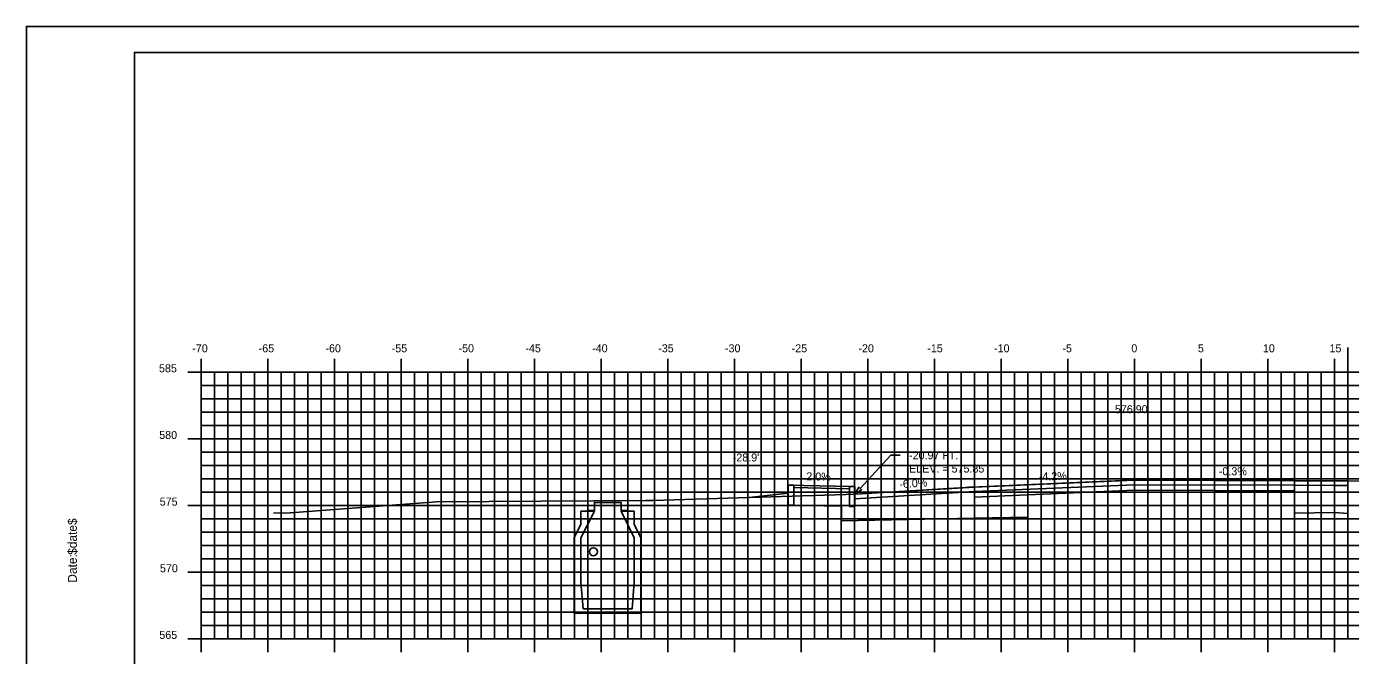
# Model space of a CAD drawing. Extents: x 1048345 to 1048515, y 781148 to 781258.
# Drawn here: x 1048344.7 to 1048444, y 781211 to 781258.2 of the extents above; entities that cross this region are included whole.
import ezdxf

# ---------------------------------------------------------------- set-up
doc = ezdxf.new("R2010")
doc.units = 0
for name, color, linetype in [('ANNOTATION', 7, 'Continuous'), ('BORDER', 7, 'Continuous'), ('D_Curb_Type1_Lt', 7, 'Continuous'), ('D_Roadway_Centerline', 7, 'Continuous'), ('D_Roadway_Centerline_Text', 7, 'Continuous'), ('D_Roadway_Edge_Shoulder', 7, 'Continuous'), ('D_Roadway_Edge_TW', 7, 'Continuous'), ('D_Roadway_Pavement', 7, 'Continuous'), ('D_Roadway_Sidewalks_Paved', 7, 'Continuous'), ('D_Roadway_SubGrade', 7, 'Continuous'), ('D_Text_Standard', 7, 'Continuous'), ('E_ROW_Line', 7, 'Continuous'), ('H_V ANNOTATION', 7, 'Continuous'), ('MAJOR', 7, 'Continuous'), ('MINOR', 7, 'Continuous'), ('PLOT BOUNDARY', 7, 'Continuous'), ('S_Drainage_CB', 7, 'Continuous'), ('S_Drainage_Invert', 7, 'Continuous'), ('S_Roadway_Centerline', 7, 'Continuous')]:
    doc.layers.add(name, color=color, linetype=linetype)

msp = doc.modelspace()

# ---------------------------------------------------------------- linework, layer by layer
at = {"layer": 'BORDER'}
msp.add_lwpolyline([(1048352.833, 781151.252), (1048512.833, 781151.252), (1048512.833, 781256.252), (1048352.833, 781256.252)], close=True, dxfattribs=at)
at = {"layer": 'D_Curb_Type1_Lt'}
for points in [[(1048401.863, 781223.78), (1048401.863, 781222.28), (1048402.28, 781222.28), (1048402.28, 781223.78)], [(1048406.445, 781223.686), (1048406.445, 781222.186), (1048406.862, 781222.186), (1048406.862, 781223.686)], [(1048406.445, 781223.686), (1048406.445, 781222.186), (1048406.862, 781222.186), (1048406.862, 781223.686)]]:
    msp.add_lwpolyline(points, close=True, dxfattribs=at)
at = {"layer": 'D_Roadway_Edge_Shoulder'}
for p, q in [((1048415.832, 781223.645), (1048406.863, 781223.102)), ((1048415.832, 781223.311), (1048406.864, 781222.769))]:
    msp.add_line(p, q, dxfattribs=at)
msp.add_lwpolyline([(1048439.832, 781224.113), (1048442.832, 781224.104), (1048443.832, 781224.101), (1048443.832, 781223.767), (1048442.832, 781223.77), (1048439.832, 781223.779)], close=True, dxfattribs=at)
at = {"layer": 'D_Roadway_Edge_TW'}
msp.add_lwpolyline([(1048415.832, 781223.311), (1048415.832, 781223.645), (1048427.832, 781224.149), (1048439.832, 781224.113), (1048439.832, 781223.779), (1048427.832, 781223.815)], close=True, dxfattribs=at)
at = {"layer": 'D_Roadway_Pavement'}
msp.add_lwpolyline([(1048415.832, 781222.895), (1048415.832, 781223.311), (1048427.832, 781223.815), (1048439.832, 781223.779), (1048439.832, 781223.363), (1048427.832, 781223.399)], close=True, dxfattribs=at)
at = {"layer": 'D_Roadway_Sidewalks_Paved'}
for points in [[(1048406.562, 781223.686), (1048401.863, 781223.78), (1048401.863, 781223.613)], [(1048406.562, 781223.686), (1048401.863, 781223.78), (1048401.863, 781223.613)], [(1048402.28, 781223.605), (1048406.445, 781223.521)], [(1048402.28, 781223.605), (1048406.445, 781223.521)]]:
    msp.add_lwpolyline(points, dxfattribs=at)
at = {"layer": 'D_Roadway_SubGrade'}
for p, q in [((1048401.863, 781223.78), (1048401.863, 781222.28)), ((1048443.832, 781224.101), (1048443.832, 781221.671)), ((1048401.863, 781223.196), (1048398.941, 781222.864)), ((1048401.863, 781222.28), (1048405.863, 781222.2)), ((1048405.863, 781222.2), (1048405.864, 781222.177))]:
    msp.add_line(p, q, dxfattribs=at)
for points in [[(1048415.832, 781223.311), (1048415.832, 781222.895), (1048419.832, 781223.063), (1048419.832, 781221.396), (1048415.832, 781221.316), (1048405.864, 781221.116), (1048405.864, 781222.177)], [(1048443.832, 781221.671), (1048442.832, 781221.747), (1048439.832, 781221.696), (1048439.832, 781223.779), (1048439.832, 781223.779), (1048442.832, 781223.77), (1048443.832, 781223.767), (1048443.832, 781223.184)]]:
    msp.add_lwpolyline(points, dxfattribs=at)
at = {"layer": 'D_Text_Standard'}
msp.add_lwpolyline([(1048407.258, 781223.53), (1048409.564, 781226.03), (1048410.244, 781226.03)], dxfattribs=at)
msp.add_lwpolyline([(1048406.863, 781223.102), (1048407.151, 781223.629), (1048407.365, 781223.431)], close=True, dxfattribs=at)
at = {"layer": 'E_ROW_Line'}
msp.add_line((1048443.832, 781224.101), (1048443.832, 781234.101), dxfattribs=at)
at = {"layer": 'MAJOR'}
for p, q in [((1048357.832, 781233.254), (1048357.832, 781232.252)), ((1048362.832, 781233.254), (1048362.832, 781232.252)), ((1048367.832, 781233.254), (1048367.832, 781232.252)), ((1048372.832, 781233.254), (1048372.832, 781232.252)), ((1048377.832, 781233.254), (1048377.832, 781232.252)), ((1048382.832, 781233.254), (1048382.832, 781232.252)), ((1048387.832, 781233.254), (1048387.832, 781232.252)), ((1048392.832, 781233.254), (1048392.832, 781232.252)), ((1048397.832, 781233.254), (1048397.832, 781232.252)), ((1048402.832, 781233.254), (1048402.832, 781232.252)), ((1048407.832, 781233.254), (1048407.832, 781232.252)), ((1048412.832, 781233.254), (1048412.832, 781232.252)), ((1048417.832, 781233.254), (1048417.832, 781232.252)), ((1048422.832, 781233.254), (1048422.832, 781232.252)), ((1048427.832, 781233.254), (1048427.832, 781232.252)), ((1048432.832, 781233.254), (1048432.832, 781232.252)), ((1048437.832, 781233.254), (1048437.832, 781232.252)), ((1048442.832, 781233.254), (1048442.832, 781232.252)), ((1048356.83, 781232.252), (1048357.832, 781232.252)), ((1048357.832, 781232.252), (1048497.832, 781232.252)), ((1048357.832, 781212.252), (1048357.832, 781232.252)), ((1048357.832, 781212.252), (1048357.832, 781232.252)), ((1048357.832, 781232.252), (1048497.832, 781232.252)), ((1048362.832, 781212.252), (1048362.832, 781232.252)), ((1048367.832, 781212.252), (1048367.832, 781232.252)), ((1048372.832, 781212.252), (1048372.832, 781232.252)), ((1048377.832, 781212.252), (1048377.832, 781232.252)), ((1048382.832, 781212.252), (1048382.832, 781232.252)), ((1048387.832, 781212.252), (1048387.832, 781232.252)), ((1048392.832, 781212.252), (1048392.832, 781232.252)), ((1048397.832, 781212.252), (1048397.832, 781232.252)), ((1048402.832, 781212.252), (1048402.832, 781232.252)), ((1048407.832, 781212.252), (1048407.832, 781232.252)), ((1048412.832, 781212.252), (1048412.832, 781232.252)), ((1048417.832, 781212.252), (1048417.832, 781232.252)), ((1048422.832, 781212.252), (1048422.832, 781232.252)), ((1048427.832, 781212.252), (1048427.832, 781232.252)), ((1048432.832, 781212.252), (1048432.832, 781232.252)), ((1048437.832, 781212.252), (1048437.832, 781232.252)), ((1048442.832, 781212.252), (1048442.832, 781232.252)), ((1048356.83, 781227.252), (1048357.832, 781227.252)), ((1048357.832, 781227.252), (1048497.832, 781227.252)), ((1048356.83, 781222.252), (1048357.832, 781222.252)), ((1048357.832, 781222.252), (1048497.832, 781222.252)), ((1048356.83, 781217.252), (1048357.832, 781217.252)), ((1048357.832, 781217.252), (1048497.832, 781217.252)), ((1048356.83, 781212.252), (1048357.832, 781212.252)), ((1048357.832, 781212.252), (1048497.832, 781212.252)), ((1048357.832, 781212.252), (1048497.832, 781212.252)), ((1048357.832, 781211.25), (1048357.832, 781212.252)), ((1048362.832, 781211.25), (1048362.832, 781212.252)), ((1048367.832, 781211.25), (1048367.832, 781212.252)), ((1048372.832, 781211.25), (1048372.832, 781212.252)), ((1048377.832, 781211.25), (1048377.832, 781212.252)), ((1048382.832, 781211.25), (1048382.832, 781212.252)), ((1048387.832, 781211.25), (1048387.832, 781212.252)), ((1048392.832, 781211.25), (1048392.832, 781212.252)), ((1048397.832, 781211.25), (1048397.832, 781212.252)), ((1048402.832, 781211.25), (1048402.832, 781212.252)), ((1048407.832, 781211.25), (1048407.832, 781212.252)), ((1048412.832, 781211.25), (1048412.832, 781212.252)), ((1048417.832, 781211.25), (1048417.832, 781212.252)), ((1048422.832, 781211.25), (1048422.832, 781212.252)), ((1048427.832, 781211.25), (1048427.832, 781212.252)), ((1048432.832, 781211.25), (1048432.832, 781212.252)), ((1048437.832, 781211.25), (1048437.832, 781212.252)), ((1048442.832, 781211.25), (1048442.832, 781212.252))]:
    msp.add_line(p, q, dxfattribs=at)
at = {"layer": 'MINOR'}
for p, q in [((1048358.832, 781212.252), (1048358.832, 781232.252)), ((1048359.832, 781212.252), (1048359.832, 781232.252)), ((1048360.832, 781212.252), (1048360.832, 781232.252)), ((1048361.832, 781212.252), (1048361.832, 781232.252)), ((1048363.832, 781212.252), (1048363.832, 781232.252)), ((1048364.832, 781212.252), (1048364.832, 781232.252)), ((1048365.832, 781212.252), (1048365.832, 781232.252)), ((1048366.832, 781212.252), (1048366.832, 781232.252)), ((1048368.832, 781212.252), (1048368.832, 781232.252)), ((1048369.832, 781212.252), (1048369.832, 781232.252)), ((1048370.832, 781212.252), (1048370.832, 781232.252)), ((1048371.832, 781212.252), (1048371.832, 781232.252)), ((1048373.832, 781212.252), (1048373.832, 781232.252)), ((1048374.832, 781212.252), (1048374.832, 781232.252)), ((1048375.832, 781212.252), (1048375.832, 781232.252)), ((1048376.832, 781212.252), (1048376.832, 781232.252)), ((1048378.832, 781212.252), (1048378.832, 781232.252)), ((1048379.832, 781212.252), (1048379.832, 781232.252)), ((1048380.832, 781212.252), (1048380.832, 781232.252)), ((1048381.832, 781212.252), (1048381.832, 781232.252)), ((1048383.832, 781212.252), (1048383.832, 781232.252)), ((1048384.832, 781212.252), (1048384.832, 781232.252)), ((1048385.832, 781212.252), (1048385.832, 781232.252)), ((1048386.832, 781212.252), (1048386.832, 781232.252)), ((1048388.832, 781212.252), (1048388.832, 781232.252)), ((1048389.832, 781212.252), (1048389.832, 781232.252)), ((1048390.832, 781212.252), (1048390.832, 781232.252)), ((1048391.832, 781212.252), (1048391.832, 781232.252)), ((1048393.832, 781212.252), (1048393.832, 781232.252)), ((1048394.832, 781212.252), (1048394.832, 781232.252)), ((1048395.832, 781212.252), (1048395.832, 781232.252)), ((1048396.832, 781212.252), (1048396.832, 781232.252)), ((1048398.832, 781212.252), (1048398.832, 781232.252)), ((1048399.832, 781212.252), (1048399.832, 781232.252)), ((1048400.832, 781212.252), (1048400.832, 781232.252)), ((1048401.832, 781212.252), (1048401.832, 781232.252)), ((1048403.832, 781212.252), (1048403.832, 781232.252)), ((1048404.832, 781212.252), (1048404.832, 781232.252)), ((1048405.832, 781212.252), (1048405.832, 781232.252)), ((1048406.832, 781212.252), (1048406.832, 781232.252)), ((1048408.832, 781212.252), (1048408.832, 781232.252)), ((1048409.832, 781212.252), (1048409.832, 781232.252)), ((1048410.832, 781212.252), (1048410.832, 781232.252)), ((1048411.832, 781212.252), (1048411.832, 781232.252)), ((1048413.832, 781212.252), (1048413.832, 781232.252)), ((1048414.832, 781212.252), (1048414.832, 781232.252)), ((1048415.832, 781212.252), (1048415.832, 781232.252)), ((1048416.832, 781212.252), (1048416.832, 781232.252)), ((1048418.832, 781212.252), (1048418.832, 781232.252)), ((1048419.832, 781212.252), (1048419.832, 781232.252)), ((1048420.832, 781212.252), (1048420.832, 781232.252)), ((1048421.832, 781212.252), (1048421.832, 781232.252)), ((1048423.832, 781212.252), (1048423.832, 781232.252)), ((1048424.832, 781212.252), (1048424.832, 781232.252)), ((1048425.832, 781212.252), (1048425.832, 781232.252)), ((1048426.832, 781212.252), (1048426.832, 781232.252)), ((1048428.832, 781212.252), (1048428.832, 781232.252)), ((1048429.832, 781212.252), (1048429.832, 781232.252)), ((1048430.832, 781212.252), (1048430.832, 781232.252)), ((1048431.832, 781212.252), (1048431.832, 781232.252)), ((1048433.832, 781212.252), (1048433.832, 781232.252)), ((1048434.832, 781212.252), (1048434.832, 781232.252)), ((1048435.832, 781212.252), (1048435.832, 781232.252)), ((1048436.832, 781212.252), (1048436.832, 781232.252)), ((1048438.832, 781212.252), (1048438.832, 781232.252)), ((1048439.832, 781212.252), (1048439.832, 781232.252)), ((1048440.832, 781212.252), (1048440.832, 781232.252)), ((1048441.832, 781212.252), (1048441.832, 781232.252)), ((1048443.832, 781212.252), (1048443.832, 781232.252)), ((1048357.832, 781231.252), (1048497.832, 781231.252)), ((1048357.832, 781231.252), (1048358.834, 781231.252)), ((1048357.832, 781230.252), (1048497.832, 781230.252)), ((1048357.832, 781230.252), (1048358.834, 781230.252)), ((1048357.832, 781229.252), (1048497.832, 781229.252)), ((1048357.832, 781229.252), (1048358.834, 781229.252)), ((1048357.832, 781228.252), (1048497.832, 781228.252)), ((1048357.832, 781228.252), (1048358.834, 781228.252)), ((1048357.832, 781226.252), (1048497.832, 781226.252)), ((1048357.832, 781226.252), (1048358.834, 781226.252)), ((1048357.832, 781225.252), (1048497.832, 781225.252)), ((1048357.832, 781225.252), (1048358.834, 781225.252)), ((1048357.832, 781224.252), (1048497.832, 781224.252)), ((1048357.832, 781224.252), (1048358.834, 781224.252)), ((1048357.832, 781223.252), (1048497.832, 781223.252)), ((1048357.832, 781223.252), (1048358.834, 781223.252)), ((1048357.832, 781221.252), (1048497.832, 781221.252)), ((1048357.832, 781221.252), (1048358.834, 781221.252)), ((1048357.832, 781220.252), (1048497.832, 781220.252)), ((1048357.832, 781220.252), (1048358.834, 781220.252)), ((1048357.832, 781219.252), (1048497.832, 781219.252)), ((1048357.832, 781219.252), (1048358.834, 781219.252)), ((1048357.832, 781218.252), (1048497.832, 781218.252)), ((1048357.832, 781218.252), (1048358.834, 781218.252)), ((1048357.832, 781216.252), (1048497.832, 781216.252)), ((1048357.832, 781216.252), (1048358.834, 781216.252)), ((1048357.832, 781215.252), (1048497.832, 781215.252)), ((1048357.832, 781215.252), (1048358.834, 781215.252)), ((1048357.832, 781214.252), (1048497.832, 781214.252)), ((1048357.832, 781214.252), (1048358.834, 781214.252)), ((1048357.832, 781213.252), (1048497.832, 781213.252)), ((1048357.832, 781213.252), (1048358.834, 781213.252))]:
    msp.add_line(p, q, dxfattribs=at)
at = {"layer": 'PLOT BOUNDARY'}
msp.add_lwpolyline([(1048344.739, 781148.193), (1048514.739, 781148.193), (1048514.739, 781258.193), (1048344.739, 781258.193)], close=True, dxfattribs=at)
at = {"layer": 'S_Drainage_CB'}
for p, q in [((1048386.314, 781220.848), (1048386.314, 781221.832)), ((1048386.314, 781221.832), (1048387.331, 781221.832)), ((1048387.331, 781221.832), (1048386.314, 781219.831)), ((1048389.332, 781221.832), (1048390.316, 781221.832)), ((1048390.316, 781219.831), (1048389.332, 781221.832)), ((1048390.316, 781221.832), (1048390.316, 781220.848)), ((1048385.822, 781219.831), (1048386.314, 781220.848)), ((1048390.316, 781220.848), (1048390.809, 781219.831)), ((1048385.822, 781214.188), (1048385.822, 781219.831)), ((1048386.314, 781219.831), (1048386.314, 781216.517)), ((1048390.316, 781216.517), (1048390.316, 781219.831)), ((1048390.809, 781219.831), (1048390.809, 781214.188)), ((1048386.314, 781216.517), (1048386.478, 781214.516)), ((1048390.152, 781214.516), (1048390.316, 781216.517)), ((1048386.478, 781214.516), (1048390.152, 781214.516)), ((1048390.809, 781214.188), (1048385.822, 781214.188))]:
    msp.add_line(p, q, dxfattribs=at)
msp.add_lwpolyline([(1048386.839, 781221.874), (1048387.331, 781221.874), (1048387.331, 781222.497), (1048389.332, 781222.497), (1048389.332, 781221.874), (1048389.824, 781221.874)], dxfattribs=at)
at = {"layer": 'S_Drainage_Invert'}
msp.add_circle((1048387.249, 781218.791), 0.3, dxfattribs=at)
at = {"layer": 'S_Roadway_Centerline'}
msp.add_lwpolyline([(1048363.274, 781221.721), (1048364.2, 781221.694), (1048375.481, 781222.541), (1048391.18, 781222.638), (1048391.541, 781222.641), (1048391.705, 781222.645), (1048406.177, 781223.083), (1048406.803, 781223.102), (1048406.858, 781223.098), (1048406.867, 781223.098), (1048406.875, 781223.098), (1048415.135, 781223.612), (1048415.407, 781223.633), (1048415.596, 781223.644), (1048427.516, 781224.148), (1048435.272, 781224.158), (1048439.732, 781224.125), (1048447.103, 781224.075)], dxfattribs=at)

# ---------------------------------------------------------------- texts
at = {"layer": 'ANNOTATION'}
for s, rotation, p in [("-28.9'", 0, (1048397.703, 781225.564)), ('2.0%', 358.85424, (1048403.216, 781224.153)), ('-6.0%', 3.60487, (1048410.213, 781223.559)), ('-4.2%', 2.40501, (1048420.668, 781224.117)), ('-0.3%', 359.82811, (1048434.153, 781224.53))]:
    msp.add_text(s, height=0.6, rotation=rotation, dxfattribs=at).set_placement(p)
at = {"layer": 'BORDER'}
for s, p in [('$date$', (1048348.517, 781218.557)), ('Date:', (1048348.517, 781216.469))]:
    msp.add_text(s, height=0.6696, rotation=90, dxfattribs=at).set_placement(p)
at = {"layer": 'D_Roadway_Centerline'}
for s, p in [('C', (1048427.827, 781224.149)), ('L', (1048427.832, 781224.141))]:
    msp.add_text(s, height=0.0146, dxfattribs=at).set_placement(p)
at = {"layer": 'D_Roadway_Centerline_Text'}
msp.add_text('576.90', height=0.6, dxfattribs=at).set_placement((1048426.361, 781229.181))
at = {"layer": 'D_Text_Standard'}
for s, p in [('-20.97 FT.', (1048410.924, 781225.73)), ('ELEV. = 575.85', (1048410.924, 781224.73))]:
    msp.add_text(s, height=0.6, dxfattribs=at).set_placement(p)
at = {"layer": 'H_V ANNOTATION'}
for s, p in [('-70', (1048357.174, 781233.752)), ('-65', (1048362.15, 781233.752)), ('-60', (1048367.158, 781233.752)), ('-55', (1048372.129, 781233.752)), ('-50', (1048377.137, 781233.752)), ('-45', (1048382.15, 781233.752)), ('-40', (1048387.158, 781233.752)), ('-35', (1048392.113, 781233.752)), ('-30', (1048397.121, 781233.752)), ('-25', (1048402.118, 781233.752)), ('-20', (1048407.126, 781233.752)), ('-15', (1048412.289, 781233.752)), ('-10', (1048417.297, 781233.752)), ('-5', (1048422.423, 781233.752)), ('0', (1048427.591, 781233.752)), ('5', (1048432.583, 781233.752)), ('10', (1048437.458, 781233.752)), ('15', (1048442.45, 781233.752)), ('585', (1048354.678, 781232.252)), ('580', (1048354.694, 781227.252)), ('575', (1048354.732, 781222.252)), ('570', (1048354.748, 781217.252)), ('565', (1048354.7, 781212.252))]:
    msp.add_text(s, height=0.6, dxfattribs=at).set_placement(p)
at = {"layer": 'MAJOR'}
msp.add_text('-', height=0.006, dxfattribs=at).set_placement((1048357.828, 781212.252))
at = {"layer": 'S_Roadway_Centerline'}
for s, p in [('L', (1048427.508, 781224.141)), ('C', (1048427.511, 781224.148))]:
    msp.add_text(s, height=0.0146, dxfattribs=at).set_placement(p)

doc.saveas('drawing.dxf')
